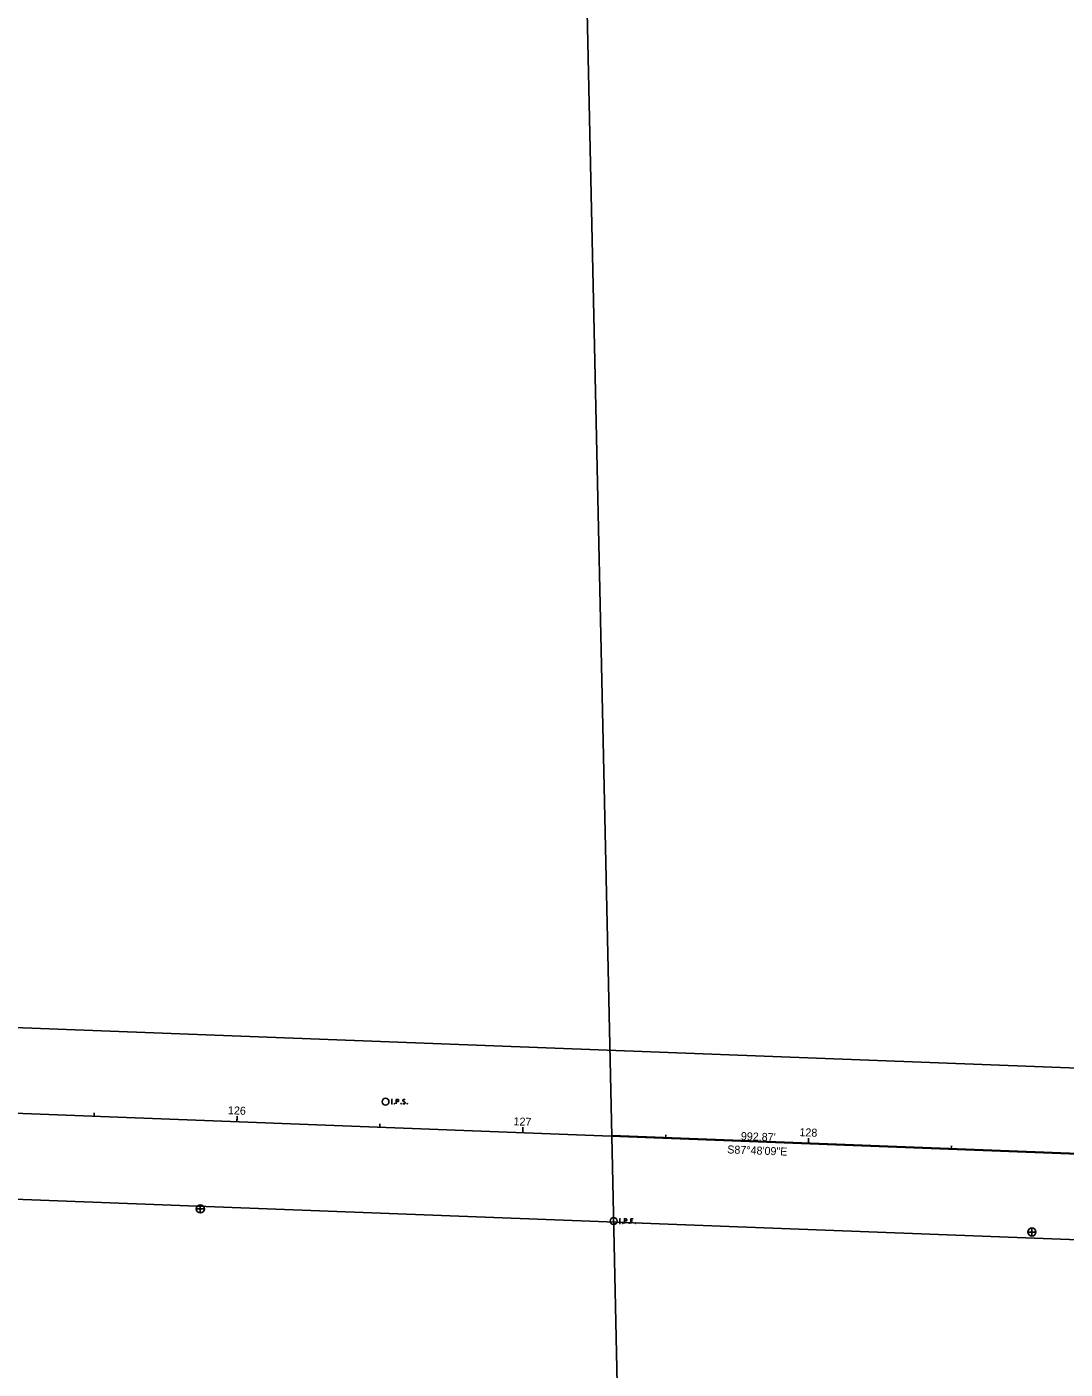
# Model space of a CAD drawing. Extents: x 2003596 to 2006888, y 571866 to 574416.
# Drawn here: x 2005260.9 to 2005624, y 572537.1 to 573006.8 of the extents above; entities that cross this region are included whole.
import ezdxf

# ---------------------------------------------------------------- set-up
doc = ezdxf.new("R2010")
doc.units = 0
for name, color, linetype in [('DV_X_Property_Line', 7, 'Continuous'), ('GE_X_Alignment', 7, 'Continuous'), ('GE_X_Alignment_1000_Bearings', 7, 'Continuous'), ('GE_X_Alignment_1000_Distances', 7, 'Continuous'), ('GE_X_Alignment_100_Bearings', 7, 'Continuous'), ('GE_X_Alignment_100_Distances', 7, 'Continuous'), ('GE_X_Alignment_100_Stations', 7, 'Continuous'), ('GE_X_Alignment_500_Bearings', 7, 'Continuous'), ('GE_X_Alignment_500_Distances', 7, 'Continuous'), ('GE_X_Alignment_500_Stations', 7, 'Continuous'), ('RW_X_CL', 7, 'Continuous'), ('RW_X_Esmt_SH', 7, 'Continuous'), ('SC_Scratch10', 7, 'Continuous'), ('SV_P_Mon_Cells_Set', 7, 'Continuous'), ('SV_X_Control_Cells_Found', 7, 'Continuous'), ('SV_X_Mon_Cells_Found', 7, 'Continuous')]:
    doc.layers.add(name, color=color, linetype=linetype)

msp = doc.modelspace()

# ---------------------------------------------------------------- linework, layer by layer
at = {"layer": 'DV_X_Property_Line'}
for p, q in [((2005446.86, 573465.01), (2005465.42, 572618.67)), ((2005465.42, 572618.67), (2005476.89, 572096))]:
    msp.add_line(p, q, dxfattribs=at)
at = {"layer": 'GE_X_Alignment'}
msp.add_line((2005031.48, 572635.32), (2006023.62, 572597.25), dxfattribs=at)
at = {"layer": 'GE_X_Alignment_100_Stations'}
for p, q in [((2005284.36, 572625.62), (2005284.41, 572626.82)), ((2005334.33, 572623.7), (2005334.4, 572625.7)), ((2005384.29, 572621.78), (2005384.34, 572622.98)), ((2005434.25, 572619.86), (2005434.33, 572621.86)), ((2005484.22, 572617.95), (2005484.26, 572619.15)), ((2005534.18, 572616.03), (2005534.26, 572618.03)), ((2005584.14, 572614.11), (2005584.19, 572615.31))]:
    msp.add_line(p, q, dxfattribs=at)
at = {"layer": 'GE_X_Alignment_500_Stations'}
for p, q in [((2005334.33, 572623.7), (2005334.37, 572624.9)), ((2005434.25, 572619.86), (2005434.3, 572621.06)), ((2005534.18, 572616.03), (2005534.23, 572617.23))]:
    msp.add_line(p, q, dxfattribs=at)
at = {"layer": 'RW_X_CL'}
msp.add_line((2006023.62, 572597.25), (2005031.48, 572635.32), dxfattribs=at)
at = {"layer": 'RW_X_Esmt_SH'}
for p, q in [((2005034.78, 572665.22), (2006024.45, 572627.24)), ((2005028.18, 572605.42), (2006022.8, 572567.26))]:
    msp.add_line(p, q, dxfattribs=at)
at = {"layer": 'SC_Scratch10'}
msp.add_line((2006023.71, 572597.25), (2005465.42, 572618.88), dxfattribs=at)
at = {"layer": 'SV_P_Mon_Cells_Set'}
for points in [[(2005388.32, 572631.54), (2005388.67, 572631.54)], [(2005388.49, 572629.94), (2005388.49, 572631.54)], [(2005390.06, 572629.94), (2005390.06, 572631.54), (2005390.59, 572631.54), (2005390.64, 572631.53), (2005390.72, 572631.5), (2005390.75, 572631.48), (2005390.79, 572631.45), (2005390.83, 572631.39), (2005390.86, 572631.33), (2005390.88, 572631.23), (2005390.88, 572631.07), (2005390.87, 572631.02), (2005390.85, 572630.95), (2005390.81, 572630.86), (2005390.76, 572630.82), (2005390.73, 572630.8), (2005390.67, 572630.77), (2005390.59, 572630.76), (2005390.06, 572630.76)], [(2005393.07, 572631.43), (2005393.05, 572631.45), (2005393.01, 572631.48), (2005392.91, 572631.52), (2005392.79, 572631.54), (2005392.7, 572631.54), (2005392.67, 572631.54), (2005392.53, 572631.5), (2005392.41, 572631.43), (2005392.33, 572631.33), (2005392.31, 572631.23), (2005392.31, 572631.15), (2005392.33, 572631.05), (2005392.42, 572630.96), (2005393.02, 572630.58), (2005393.08, 572630.53), (2005393.1, 572630.48), (2005393.12, 572630.41), (2005393.12, 572630.33), (2005393.11, 572630.26), (2005393.1, 572630.21), (2005393.08, 572630.14), (2005393.06, 572630.09), (2005393.03, 572630.05), (2005393, 572630.02), (2005392.97, 572629.99), (2005392.92, 572629.97), (2005392.89, 572629.95), (2005392.79, 572629.94), (2005392.64, 572629.94), (2005392.54, 572629.97), (2005392.39, 572630.05), (2005392.31, 572630.13)], [(2005388.32, 572629.94), (2005388.67, 572629.94)], [(2005389.45, 572630.15), (2005389.51, 572630.15), (2005389.54, 572630.13), (2005389.57, 572630.08), (2005389.57, 572630.02), (2005389.54, 572629.97), (2005389.51, 572629.94), (2005389.45, 572629.94), (2005389.42, 572629.97), (2005389.39, 572630.02), (2005389.39, 572630.08), (2005389.42, 572630.13), (2005389.45, 572630.15)], [(2005391.7, 572630.15), (2005391.76, 572630.15), (2005391.79, 572630.13), (2005391.82, 572630.08), (2005391.82, 572630.02), (2005391.79, 572629.97), (2005391.76, 572629.94), (2005391.7, 572629.94), (2005391.67, 572629.97), (2005391.63, 572630.02), (2005391.63, 572630.08), (2005391.67, 572630.13), (2005391.7, 572630.15)], [(2005393.88, 572630.15), (2005393.94, 572630.15), (2005393.97, 572630.13), (2005394, 572630.08), (2005394, 572630.02), (2005393.97, 572629.97), (2005393.94, 572629.94), (2005393.88, 572629.94), (2005393.85, 572629.97), (2005393.82, 572630.02), (2005393.82, 572630.08), (2005393.85, 572630.13), (2005393.88, 572630.15)]]:
    msp.add_lwpolyline(points, dxfattribs=at)
msp.add_circle((2005386.3, 572630.74), 1.2, dxfattribs=at)
at = {"layer": 'SV_X_Control_Cells_Found'}
for p, q in [((2005321.51, 572594.62), (2005321.51, 572591.8)), ((2005320.1, 572593.21), (2005322.92, 572593.21)), ((2005610.94, 572585.14), (2005613.76, 572585.14)), ((2005612.35, 572586.55), (2005612.35, 572583.73))]:
    msp.add_line(p, q, dxfattribs=at)
for centre in [(2005321.51, 572593.21), (2005612.35, 572585.14)]:
    msp.add_circle(centre, 1.41, dxfattribs=at)
at = {"layer": 'SV_X_Mon_Cells_Found'}
for points in [[(2005468.09, 572589.77), (2005468.44, 572589.77)], [(2005468.27, 572588.17), (2005468.27, 572589.77)], [(2005469.83, 572588.17), (2005469.83, 572589.77), (2005470.36, 572589.77), (2005470.42, 572589.76), (2005470.49, 572589.73), (2005470.53, 572589.71), (2005470.56, 572589.68), (2005470.6, 572589.62), (2005470.64, 572589.56), (2005470.66, 572589.46), (2005470.66, 572589.31), (2005470.65, 572589.25), (2005470.62, 572589.18), (2005470.58, 572589.09), (2005470.54, 572589.05), (2005470.5, 572589.03), (2005470.45, 572589), (2005470.36, 572588.99), (2005469.83, 572588.99)], [(2005472.84, 572589.77), (2005472.08, 572589.77), (2005472.08, 572588.17)], [(2005472.08, 572588.99), (2005472.62, 572588.99)], [(2005468.09, 572588.17), (2005468.44, 572588.17)], [(2005469.22, 572588.39), (2005469.28, 572588.39), (2005469.31, 572588.36), (2005469.35, 572588.31), (2005469.35, 572588.25), (2005469.31, 572588.2), (2005469.28, 572588.17), (2005469.22, 572588.17), (2005469.19, 572588.2), (2005469.16, 572588.25), (2005469.16, 572588.31), (2005469.19, 572588.36), (2005469.22, 572588.39)], [(2005471.47, 572588.39), (2005471.53, 572588.39), (2005471.56, 572588.36), (2005471.59, 572588.31), (2005471.59, 572588.25), (2005471.56, 572588.2), (2005471.53, 572588.17), (2005471.47, 572588.17), (2005471.44, 572588.2), (2005471.41, 572588.25), (2005471.41, 572588.31), (2005471.44, 572588.36), (2005471.47, 572588.39)], [(2005473.62, 572588.39), (2005473.68, 572588.39), (2005473.71, 572588.36), (2005473.74, 572588.31), (2005473.74, 572588.25), (2005473.71, 572588.2), (2005473.68, 572588.17), (2005473.62, 572588.17), (2005473.59, 572588.2), (2005473.56, 572588.25), (2005473.56, 572588.31), (2005473.59, 572588.36), (2005473.62, 572588.39)]]:
    msp.add_lwpolyline(points, dxfattribs=at)
msp.add_circle((2005466.07, 572588.97), 1.2, dxfattribs=at)

# ---------------------------------------------------------------- texts
at = {"layer": 'GE_X_Alignment_1000_Bearings'}
msp.add_text('S87°48\'09"E', height=2.8, rotation=357.8026, dxfattribs=at).set_placement((2005505.75, 572612.66))
at = {"layer": 'GE_X_Alignment_1000_Distances'}
msp.add_text("992.87'", height=2.8, rotation=357.8026, dxfattribs=at).set_placement((2005510.52, 572617.33))
at = {"layer": 'GE_X_Alignment_100_Bearings'}
msp.add_text('S87°48\'09"E', height=2.8, rotation=357.8026, dxfattribs=at).set_placement((2005505.75, 572612.66))
at = {"layer": 'GE_X_Alignment_100_Distances'}
msp.add_text("992.87'", height=2.8, rotation=357.8026, dxfattribs=at).set_placement((2005510.52, 572617.33))
at = {"layer": 'GE_X_Alignment_100_Stations'}
for s, p in [('126', (2005331.14, 572626.37)), ('127', (2005431.01, 572622.49)), ('128', (2005531, 572618.7))]:
    msp.add_text(s, height=2.8, rotation=357.8026, dxfattribs=at).set_placement(p)
at = {"layer": 'GE_X_Alignment_500_Bearings'}
msp.add_text('S87°48\'09"E', height=2.8, rotation=357.8026, dxfattribs=at).set_placement((2005505.75, 572612.66))
at = {"layer": 'GE_X_Alignment_500_Distances'}
msp.add_text("992.87'", height=2.8, rotation=357.8026, dxfattribs=at).set_placement((2005510.52, 572617.33))

doc.saveas('drawing.dxf')
